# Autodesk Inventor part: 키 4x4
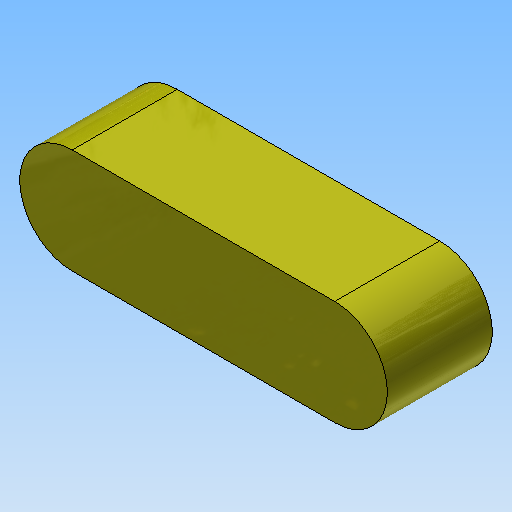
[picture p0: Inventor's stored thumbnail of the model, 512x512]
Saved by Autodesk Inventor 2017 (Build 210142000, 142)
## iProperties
Created: 2018-09
Part Number: 키 4x4
Document SubType Name: Modeling
Density: 7.86 g/cm^3
Material: 강철, 연강
Appearance: 노란색
Mass: 1.65269 g
Surface Area: 2.35398 cm^2
Volume: 0.210265 cm^3
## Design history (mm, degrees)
sketch "스케치1"
  geometry: L1 (-5, -2)-(5, -2); L2 (5, 2)-(-5, 2); A1 r 2 centre (5, 0) between (5, -2) and (5, 2); A2 r 2 centre (-5, 0) between (-5, 2) and (-5, -2); 2 further points
  constraints: 4 end point, 4 point on circle, 4 tangent, 2 centre point, 1 horizontal, 1 horizontal alignment, 1 midpoint, 1 parallel, 1 vertical alignment
  dimensions: "d0" = 4 distance between parallel lines of L1 L2; "d1" = 14 dimension on A1 A2
extrude "돌출1" new body sketch "스케치1" stored distance "d2" = 4; taper "d3" = 0 deg
node "솔리드1"
